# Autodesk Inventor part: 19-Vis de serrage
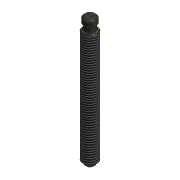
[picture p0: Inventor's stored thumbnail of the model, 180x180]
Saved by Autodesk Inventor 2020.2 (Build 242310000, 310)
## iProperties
Created: 2022-03
Part Number: 19-Vis de serrage
Material: Acier
Document SubType Name: Modeling
Designer: %USERNAME%
Density: 7.85 g/cm^3
Appearance: Plaque
Author: %USERNAME%
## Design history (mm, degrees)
sketch "Esquisse2"
  geometry: L1 (0, 0)-(5, 0); L2 (5, 0)-(5, 90); L3 (5, 90)-(0, 90); L4 (0, 90)-(0, 0); L5 (5, 86)-(3.5, 86); L6 (3.5, 86)-(3.5, 82); L7 (3.5, 82)-(5, 82); L8 (5, 82)-(5, 86); L9 (3.5, 86)-(4.25, 86); L10 (4.25, 86)-(4.25, 90); L11 (4.25, 90)-(3.5, 90); L12 (3.5, 90)-(3.5, 86); L13 (5, 0)-(3.5, 0); L14 (3.5, 0)-(3.5, 2); L15 (3.5, 2)-(5, 2); L16 (5, 2)-(5, 0); 4 further points
  constraints: 32 end point, 8 parallel, 4 horizontal, 4 perpendicular, 3 point on line, 1 midpoint
  dimensions: "d0" = 10 diameter of L2 L4; "d1" = 90 distance of L1.end L2.end; "d3" = 7 diameter of L6 L4; "d4" = 4 distance of L9.end L10.end; "d5" = 4 distance of L5.end L6.end; "d11" = 2 distance of L13.end L14.end; "d12" = 7 diameter of L14 L4
revolve "Révolution1" sketch "Esquisse2" stored, may be unused: angle "d2" = 90 deg
chamfer "Chanfrein1" distance "d6" = 1; stored, may be unused: second distance "d7" = 2, angle "d8" = 45 deg
feature "Filetage1" dims "d9" = 85, "d10" = 0
sketch "Esquisse3"
  geometry: A1 r 4.25 centre (0, 0) between (0, 4.25) and (4.25, 0); 1 further point
  constraints: 2 point on circle, 1 centre point, 1 coincident
  dimensions: "d13" = 4.25 radius of A1
feature "SrfExtrusion1" sketch "Esquisse3" dims "d14" = 80, "d15" = 0
node "Solide1"
body "Srf1"
